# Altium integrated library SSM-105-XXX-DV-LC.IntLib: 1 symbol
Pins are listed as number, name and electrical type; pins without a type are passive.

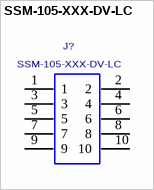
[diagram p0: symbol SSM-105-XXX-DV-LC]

## SSM-105-XXX-DV-LC
designator J?
Socket Strip, Surface Mount, Double Row ,0.100" Pitch, 10 PINS.; MANUFACTURER: SAMTEC
footprint SSM-105-XXX-DV-LC
pins: 1, 2, 3, 4, 5, 6, 7, 8, 9, 10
